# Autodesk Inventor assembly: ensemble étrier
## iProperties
Shininess: 64.0
Length Units: 11269
Angle Units: 11279
Time Units: 11290
Mass Units: 11283
Length Display Precision: 3
Angle Display Precision: 2
Compacted: True
Created: 2004-12
Part Number: ensemble étrier
Document SubType Name: Assembly
Designer: LEGERET Philippe
Density: 0.0
Volumn: 0.0
Area: 0.0
PropertySet Name: Model Information
Control State: 0
Master: False
Checked Out: False
Author: LEGERET Philippe
